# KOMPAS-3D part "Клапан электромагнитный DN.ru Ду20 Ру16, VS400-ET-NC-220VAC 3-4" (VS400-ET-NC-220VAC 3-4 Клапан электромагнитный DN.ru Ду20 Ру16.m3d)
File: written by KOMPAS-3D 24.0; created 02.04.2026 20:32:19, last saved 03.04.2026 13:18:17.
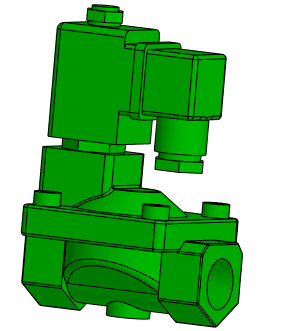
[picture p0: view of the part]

Document properties: Автор: artio; Полное имя файла: C:\Users\artio\OneDrive\Рабочий стол\Клапан электромагнитный DN.ru\VS400-ET-NC-220VAC 3-4 Клапан электромагнитный DN.ru Ду20 Ру16.m3d

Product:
- Body: Тело 1  | qty 1
    Масса: 1.210539
- Part/product: Клапан электромагнитный DN.ru Ду20 Ру16  | designation VS400-ET-NC-220VAC 3-4
    Масса: 0.954
    Раздел спецификации: Прочие изделия
    Примечание: D130-04692
    additional columns: ef56311e-7521-43dc-8291-0e6108b3d81d; VS400-ET-NC-220VAC 3-4; artio; c; Шероховатость не задана; Да

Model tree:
1. Операция без истории:1

Expressions: VS400-ET-NC-220VAC 3-4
